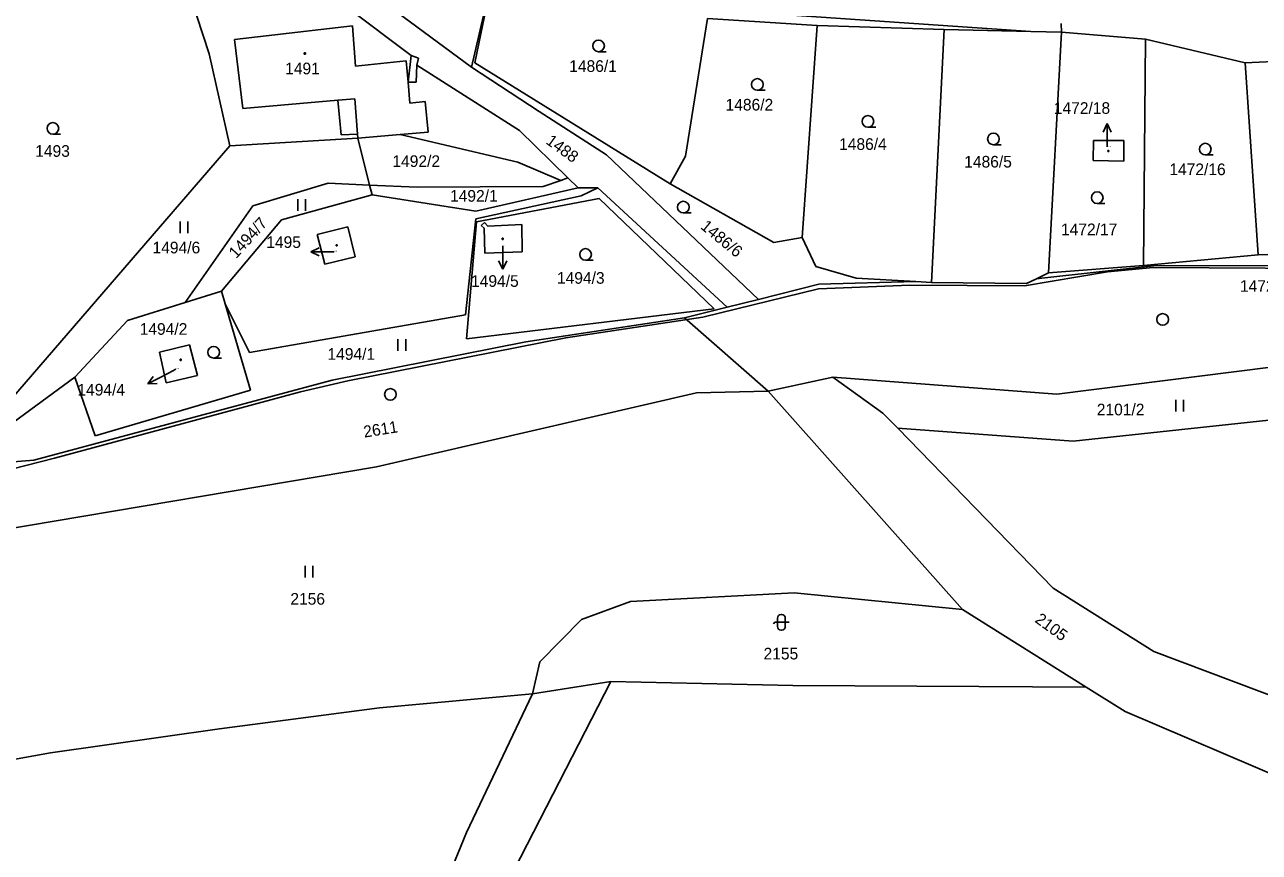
# Model space of a CAD drawing. Extents: x -805730 to -804640, y -1150889 to -1150366.
# Drawn here: x -805353.5 to -805194.5, y -1150727 to -1150620.5 of the extents above; entities that cross this region are included whole.
import ezdxf

# ---------------------------------------------------------------- set-up
doc = ezdxf.new("R2010")
doc.units = 0
for name, color, linetype in [('Default', 7, 'Continuous'), ('kilometráž - vrstava 7', 7, 'Continuous'), ('kn_celek - Cisla parcel pomocna', 7, 'Continuous'), ('kn_celek - Cisla pozemkovych parcel', 7, 'Continuous'), ('kn_celek - Cisla stavebnich parcel', 7, 'Continuous'), ('kn_celek - Hranice parcel', 7, 'Continuous'), ('kn_celek - Vnitrni kresby', 7, 'Continuous'), ('kn_celek - Znacky budov', 7, 'Continuous'), ('kn_celek - Znacky kultur', 7, 'Continuous'), ('plochy - SZDC', 7, 'Continuous'), ('PSR_C2_2_trasa_Vimperk - Kabelová trasa', 7, 'Continuous')]:
    doc.layers.add(name, color=color, linetype=linetype)

# ---------------------------------------------------------------- blocks, each defined once
blk = doc.blocks.new('304')
at = {"layer": 'Default'}
blk.add_line((-0.1, 0), (9.9, 0), dxfattribs=at)
blk.add_circle((-0.1, 7.5), 7.5, dxfattribs=at)
blk = doc.blocks.new('306')
at = {"layer": 'Default'}
for p, q in [((-5.2, 0), (-5.2, 15)), ((4.8, 0), (4.8, 15))]:
    blk.add_line(p, q, dxfattribs=at)
blk = doc.blocks.new('316')
at = {"layer": 'Default'}
for p, q in [((0.5, 20), (-0.5, 20)), ((-8.3, 10), (-10, 8.1)), ((-5, 10), (-8.3, 10)), ((-5, 15.5), (-5, 4.5)), ((-5, 10), (5, 10)), ((-0.5, 0), (0.5, 0)), ((5, 4.5), (5, 15.5)), ((10, 10), (5, 10))]:
    blk.add_line(p, q, dxfattribs=at)
for centre, start, end in [((-0.5, 15.5), 90, 180), ((0.5, 15.5), 0, 90), ((-0.5, 4.5), 180, 270), ((0.5, 4.5), 270, 0)]:
    blk.add_arc(centre, 4.5, start, end, dxfattribs=at)
blk = doc.blocks.new('402')
at = {"layer": 'Default'}
for p, q in [((-0.8, 0.8), (0.7, 0.8)), ((-0.8, 0.8), (-0.8, -0.7)), ((0.7, 0.8), (0.7, -0.7)), ((0.7, -0.7), (-0.8, -0.7))]:
    blk.add_line(p, q, dxfattribs=at)
blk = doc.blocks.new('Z61')
at = {"layer": 'Default'}
for p, q in [((0, 0), (30, 0)), ((30, 0), (19.2, 5.3)), ((30, 0), (19.2, -5.3))]:
    blk.add_line(p, q, dxfattribs=at)

msp = doc.modelspace()

# ---------------------------------------------------------------- linework, layer by layer
at = {"layer": 'kilometráž - vrstava 7'}
for centre in [(-805206.98, -1150658.41), (-805306.42, -1150668.06)]:
    msp.add_circle(centre, 0.75, dxfattribs=at)
at = {"layer": 'kn_celek - Cisla parcel pomocna'}
msp.add_line((-805334.06, -1150664.81), (-805335, -1150665.31), dxfattribs=at)
at = {"layer": 'kn_celek - Hranice parcel'}
for p, q in [((-805329.77, -1150624.22), (-805333.04, -1150614.16)), ((-805310.84, -1150614.97), (-805295.98, -1150625.93)), ((-805295.98, -1150625.93), (-805293.82, -1150616.59)), ((-805293.75, -1150616.59), (-805295.53, -1150625.4)), ((-805303.74, -1150624.45), (-805312.03, -1150618.23)), ((-805272.94, -1150618.01), (-805223.94, -1150621.35)), ((-805265.57, -1150619.68), (-805268.41, -1150637.4)), ((-805265.57, -1150619.68), (-805251.46, -1150620.59)), ((-805253.39, -1150647.87), (-805251.46, -1150620.59)), ((-805251.46, -1150620.59), (-805235.12, -1150621.11)), ((-805235.12, -1150621.11), (-805236.73, -1150653.66)), ((-805235.12, -1150621.11), (-805223.94, -1150621.35)), ((-805220.01, -1150621.44), (-805223.94, -1150621.35)), ((-805220.01, -1150621.44), (-805221.67, -1150652.43)), ((-805220.01, -1150621.44), (-805220.03, -1150620.31)), ((-805220.01, -1150621.44), (-805209.21, -1150622.35)), ((-805209.21, -1150622.35), (-805209.44, -1150651.45)), ((-805209.21, -1150622.35), (-805196.37, -1150625.39)), ((-805329.77, -1150624.22), (-805327.08, -1150636.08)), ((-805303.74, -1150624.45), (-805302.8, -1150624.78)), ((-805302.8, -1150624.78), (-805303.02, -1150625.67)), ((-805196.37, -1150625.39), (-805183.26, -1150624.76)), ((-805289.81, -1150634.11), (-805303.02, -1150625.67)), ((-805295.98, -1150625.93), (-805287.25, -1150631.65)), ((-805270.38, -1150640.96), (-805295.53, -1150625.4)), ((-805196.37, -1150625.39), (-805194.7, -1150650.11)), ((-805287.25, -1150631.65), (-805278.6, -1150637.23)), ((-805283.55, -1150640.18), (-805289.81, -1150634.11)), ((-805310.6, -1150635.06), (-805327.08, -1150636.08)), ((-805310.6, -1150635.06), (-805305.16, -1150634.61)), ((-805309.1, -1150641.11), (-805310.6, -1150635.06)), ((-805305.16, -1150634.61), (-805290, -1150638.16)), ((-805215.94, -1150637.96), (-805215.89, -1150635.38)), ((-805215.89, -1150635.38), (-805212, -1150635.4)), ((-805212, -1150635.4), (-805212, -1150638.05)), ((-805362.8, -1150677.38), (-805327.08, -1150636.08)), ((-805278.6, -1150637.23), (-805259.03, -1150655.84)), ((-805268.41, -1150637.4), (-805270.38, -1150640.96)), ((-805284.49, -1150640.51), (-805290, -1150638.16)), ((-805212, -1150638.05), (-805215.94, -1150637.96)), ((-805286.74, -1150641.29), (-805284.49, -1150640.51)), ((-805284.49, -1150640.51), (-805283.55, -1150640.18)), ((-805282.22, -1150641.47), (-805283.55, -1150640.18)), ((-805314.43, -1150640.89), (-805324.14, -1150643.77)), ((-805320.46, -1150645.58), (-805308.78, -1150642.39)), ((-805309.1, -1150641.11), (-805314.43, -1150640.89)), ((-805308.78, -1150642.39), (-805309.1, -1150641.11)), ((-805302.95, -1150641.37), (-805309.1, -1150641.11)), ((-805308.78, -1150642.39), (-805295.4, -1150644.46)), ((-805286.74, -1150641.29), (-805302.95, -1150641.37)), ((-805295.4, -1150644.46), (-805282.22, -1150641.47)), ((-805282.22, -1150641.47), (-805279.69, -1150641.49)), ((-805279.69, -1150641.49), (-805281.84, -1150642.49)), ((-805279.69, -1150641.49), (-805263.04, -1150656.84)), ((-805270.38, -1150640.96), (-805257.03, -1150648.53)), ((-805324.14, -1150643.77), (-805332.84, -1150656.24)), ((-805295.42, -1150645.46), (-805281.84, -1150642.49)), ((-805279.55, -1150642.84), (-805295.32, -1150645.83)), ((-805279.55, -1150642.84), (-805264.71, -1150657.04)), ((-805328.16, -1150654.79), (-805320.46, -1150645.58)), ((-805295.42, -1150645.46), (-805296.73, -1150657.84)), ((-805295.32, -1150645.83), (-805296.63, -1150660.91)), ((-805294.74, -1150646.34), (-805294.28, -1150645.95)), ((-805294.35, -1150646.65), (-805294.74, -1150646.34)), ((-805294.25, -1150649.87), (-805294.35, -1150646.65)), ((-805294.28, -1150645.95), (-805293.87, -1150646.39)), ((-805293.87, -1150646.39), (-805289.51, -1150646.21)), ((-805289.51, -1150646.21), (-805289.44, -1150649.72)), ((-805257.03, -1150648.53), (-805253.39, -1150647.87)), ((-805251.65, -1150651.59), (-805253.39, -1150647.87)), ((-805289.44, -1150649.72), (-805294.25, -1150649.87)), ((-805209.44, -1150651.45), (-805194.7, -1150650.11)), ((-805194.7, -1150650.11), (-805180.04, -1150649.49)), ((-805246.46, -1150653.1), (-805251.65, -1150651.59)), ((-805222.55, -1150653.1), (-805208.17, -1150651.53)), ((-805221.67, -1150652.43), (-805209.44, -1150651.45)), ((-805178.93, -1150651.45), (-805208.17, -1150651.53)), ((-805238.75, -1150653.54), (-805246.46, -1150653.1)), ((-805223.22, -1150653.17), (-805224.51, -1150653.79)), ((-805221.67, -1150652.43), (-805223.22, -1150653.17)), ((-805223.22, -1150653.17), (-805222.55, -1150653.1)), ((-805332.84, -1150656.24), (-805328.16, -1150654.79)), ((-805328.16, -1150654.79), (-805327.68, -1150656.42)), ((-805259.03, -1150655.84), (-805251.25, -1150653.89)), ((-805251.25, -1150653.89), (-805238.75, -1150653.54)), ((-805236.73, -1150653.66), (-805238.75, -1150653.54)), ((-805224.51, -1150653.79), (-805236.73, -1150653.66)), ((-805340.26, -1150658.54), (-805332.84, -1150656.24)), ((-805327.68, -1150656.42), (-805324.43, -1150667.5)), ((-805327.68, -1150656.42), (-805324.56, -1150662.66)), ((-805263.04, -1150656.84), (-805259.03, -1150655.84)), ((-805296.73, -1150657.84), (-805324.56, -1150662.66)), ((-805296.63, -1150660.91), (-805264.71, -1150657.04)), ((-805288.99, -1150661.29), (-805268.53, -1150658.22)), ((-805268.53, -1150658.22), (-805263.04, -1150656.84)), ((-805268.53, -1150658.22), (-805257.77, -1150667.64)), ((-805347.06, -1150665.86), (-805340.26, -1150658.54)), ((-805313.93, -1150666.21), (-805288.99, -1150661.29)), ((-805336.17, -1150662.61), (-805332.28, -1150661.68)), ((-805335.28, -1150666.58), (-805336.17, -1150662.61)), ((-805332.28, -1150661.68), (-805331.27, -1150665.63)), ((-805220.59, -1150668.04), (-805193.03, -1150664.54)), ((-805362.8, -1150677.38), (-805347.06, -1150665.86)), ((-805313.93, -1150666.21), (-805352.32, -1150676.52)), ((-805344.42, -1150673.39), (-805347.06, -1150665.86)), ((-805331.27, -1150665.63), (-805335.28, -1150666.58)), ((-805257.77, -1150667.64), (-805249.45, -1150665.86)), ((-805249.45, -1150665.86), (-805220.59, -1150668.04)), ((-805249.45, -1150665.86), (-805243, -1150670.46)), ((-805344.42, -1150673.39), (-805324.43, -1150667.5)), ((-805267.02, -1150667.87), (-805257.77, -1150667.64)), ((-805257.77, -1150667.64), (-805232.77, -1150695.74)), ((-805308.19, -1150677.39), (-805267.02, -1150667.87)), ((-805243, -1150670.46), (-805241.07, -1150672.41)), ((-805218.5, -1150674.08), (-805189.9, -1150671)), ((-805241.07, -1150672.41), (-805218.5, -1150674.08)), ((-805241.07, -1150672.41), (-805221.06, -1150693)), ((-805362.8, -1150677.38), (-805352.32, -1150676.52)), ((-805358.57, -1150685.85), (-805308.19, -1150677.39)), ((-805221.06, -1150693), (-805208.12, -1150701.15)), ((-805281.82, -1150697.05), (-805275.5, -1150694.72)), ((-805275.5, -1150694.72), (-805254.41, -1150693.59)), ((-805232.77, -1150695.74), (-805254.41, -1150693.59)), ((-805232.77, -1150695.74), (-805216.83, -1150705.76)), ((-805287.18, -1150702.5), (-805281.82, -1150697.05)), ((-805208.12, -1150701.15), (-805186.47, -1150709.31)), ((-805288.11, -1150706.61), (-805287.18, -1150702.5)), ((-805278.05, -1150705.01), (-805290.48, -1150729.27)), ((-805278.05, -1150705.01), (-805288.11, -1150706.61)), ((-805254.58, -1150705.52), (-805278.05, -1150705.01)), ((-805230.66, -1150705.67), (-805254.58, -1150705.52)), ((-805216.83, -1150705.76), (-805230.66, -1150705.67)), ((-805211.82, -1150708.9), (-805216.83, -1150705.76)), ((-805307.83, -1150708.43), (-805288.11, -1150706.61)), ((-805296.6, -1150724.44), (-805288.11, -1150706.61)), ((-805328.43, -1150711.11), (-805307.83, -1150708.43)), ((-805185.27, -1150720.22), (-805211.82, -1150708.9)), ((-805350.19, -1150714.2), (-805328.43, -1150711.11)), ((-805369.54, -1150717.67), (-805350.19, -1150714.2)), ((-805305.52, -1150746.02), (-805296.6, -1150724.44))]:
    msp.add_line(p, q, dxfattribs=at)
at = {"layer": 'kn_celek - Vnitrni kresby'}
for p, q in [((-805326.49, -1150622.4), (-805311.29, -1150620.64)), ((-805311.29, -1150620.64), (-805310.93, -1150625.8)), ((-805325.44, -1150631.26), (-805326.49, -1150622.4)), ((-805303.74, -1150624.45), (-805304.15, -1150627.87)), ((-805310.93, -1150625.8), (-805304.38, -1150625.11)), ((-805304.38, -1150625.11), (-805304.15, -1150627.87)), ((-805303.02, -1150625.67), (-805303.1, -1150627.89)), ((-805303.1, -1150627.89), (-805304.15, -1150627.87)), ((-805304.15, -1150627.87), (-805303.92, -1150630.59)), ((-805325.44, -1150631.26), (-805313.18, -1150630.2)), ((-805313.18, -1150630.2), (-805311.01, -1150630.01)), ((-805312.75, -1150634.63), (-805313.18, -1150630.2)), ((-805310.64, -1150634.56), (-805311.01, -1150630.01)), ((-805303.92, -1150630.59), (-805301.96, -1150630.37)), ((-805301.96, -1150630.37), (-805301.56, -1150634.32)), ((-805301.56, -1150634.32), (-805305.16, -1150634.61)), ((-805310.64, -1150634.56), (-805312.75, -1150634.63)), ((-805310.6, -1150635.06), (-805310.64, -1150634.56)), ((-805315.86, -1150647.46), (-805311.91, -1150646.48)), ((-805311.91, -1150646.48), (-805310.94, -1150650.34)), ((-805314.84, -1150651.32), (-805315.86, -1150647.46)), ((-805310.94, -1150650.34), (-805314.84, -1150651.32))]:
    msp.add_line(p, q, dxfattribs=at)
at = {"layer": 'plochy - SZDC'}
for p, q in [((-805208.17, -1150651.53), (-805222.55, -1150653.1)), ((-805178.93, -1150651.45), (-805208.17, -1150651.53)), ((-805223.22, -1150653.17), (-805224.51, -1150653.79)), ((-805222.55, -1150653.1), (-805223.22, -1150653.17)), ((-805251.25, -1150653.89), (-805259.03, -1150655.84)), ((-805238.75, -1150653.54), (-805251.25, -1150653.89)), ((-805236.73, -1150653.66), (-805238.75, -1150653.54)), ((-805224.51, -1150653.79), (-805236.73, -1150653.66)), ((-805259.03, -1150655.84), (-805263.04, -1150656.84)), ((-805268.53, -1150658.22), (-805288.99, -1150661.29)), ((-805263.04, -1150656.84), (-805268.53, -1150658.22)), ((-805257.77, -1150667.64), (-805268.53, -1150658.22)), ((-805268.53, -1150658.22), (-805257.77, -1150667.64)), ((-805288.99, -1150661.29), (-805313.93, -1150666.21)), ((-805220.59, -1150668.04), (-805193.03, -1150664.54)), ((-805313.93, -1150666.21), (-805352.32, -1150676.52)), ((-805257.77, -1150667.64), (-805249.45, -1150665.86)), ((-805249.45, -1150665.86), (-805220.59, -1150668.04)), ((-805267.02, -1150667.87), (-805257.77, -1150667.64)), ((-805308.19, -1150677.39), (-805267.02, -1150667.87)), ((-805352.32, -1150676.52), (-805362.8, -1150677.38)), ((-805358.57, -1150685.85), (-805308.19, -1150677.39))]:
    msp.add_line(p, q, dxfattribs=at)
at = {"layer": 'PSR_C2_2_trasa_Vimperk - Kabelová trasa'}
for points in [[(-805214.1, -1150652.28), (-805208.19, -1150651.74), (-805179.31, -1150651.91), (-805164.88, -1150649.95), (-805150.36, -1150646.9), (-805138.79, -1150644.66), (-805134.9, -1150644.97), (-805132.95, -1150644.53), (-805122.45, -1150641.59)], [(-805239.52, -1150653.99), (-805224.76, -1150654.07), (-805214.1, -1150652.28)], [(-805372.22, -1150682.03), (-805349.68, -1150676.27), (-805317.98, -1150667.75), (-805311.89, -1150666.33), (-805283.81, -1150660.76), (-805266.17, -1150658.11), (-805251.29, -1150654.49), (-805239.52, -1150653.99)]]:
    msp.add_lwpolyline(points, dxfattribs=at)

# ---------------------------------------------------------------- block references
at = {"layer": 'kn_celek - Cisla parcel pomocna', "xscale": 0.1}
for p, yscale, rotation in [((-805214.13, -1150636.21), 0.10000000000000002, 90.00000000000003), ((-805313.65, -1150649.71), 0.10000000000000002, -179.99999999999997), ((-805291.95, -1150648.96), 0.10000000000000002, -90.00000000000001), ((-805335, -1150665.31), 0.09999999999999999, -152.11008000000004)]:
    msp.add_blockref('Z61', p, dxfattribs=dict(at, yscale=yscale, rotation=rotation))
at = {"layer": 'kn_celek - Znacky budov', "xscale": 0.1, "yscale": 0.10000000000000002}
for p in [(-805317.43, -1150624.19), (-805213.96, -1150636.74), (-805291.95, -1150648.04), (-805313.33, -1150648.89), (-805333.42, -1150663.62)]:
    msp.add_blockref('402', p, dxfattribs=at)
at = {"layer": 'kn_celek - Znacky kultur', "xscale": 0.1, "yscale": 0.10000000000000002}
for name, p in [('304', (-805279.61, -1150623.95)), ('304', (-805259.16, -1150628.92)), ('304', (-805244.92, -1150633.67)), ('304', (-805349.87, -1150634.57)), ('304', (-805228.76, -1150635.93)), ('304', (-805201.48, -1150637.24)), ('304', (-805215.4, -1150643.49)), ('306', (-805317.83, -1150644.42)), ('304', (-805268.69, -1150644.71)), ('306', (-805332.98, -1150647.31)), ('304', (-805281.28, -1150650.8)), ('306', (-805304.93, -1150662.45)), ('304', (-805329.16, -1150663.39)), ('306', (-805204.77, -1150670.27)), ('306', (-805316.89, -1150691.64)), ('316', (-805256.07, -1150698.4))]:
    msp.add_blockref(name, p, dxfattribs=at)

# ---------------------------------------------------------------- texts
at = {"layer": 'kn_celek - Cisla parcel pomocna'}
for s, p in [('1472/18', (-805220.99, -1150631.95)), ('1495', (-805322.4, -1150649.21)), ('1494/5', (-805296.03, -1150654.22)), ('1472/21', (-805197.03, -1150654.86)), ('1494/4', (-805346.72, -1150668.21))]:
    msp.add_text(s, height=1.5, dxfattribs=at).set_placement(p)
at = {"layer": 'kn_celek - Cisla pozemkovych parcel'}
for s, p in [('1486/1', (-805283.39, -1150626.55)), ('1486/2', (-805263.26, -1150631.52)), ('1493', (-805352.15, -1150637.48)), ('1486/4', (-805248.64, -1150636.59)), ('1492/2', (-805306.16, -1150638.79)), ('1486/5', (-805232.53, -1150638.86)), ('1472/16', (-805206.12, -1150639.84)), ('1492/1', (-805298.74, -1150643.26)), ('1472/17', (-805220.07, -1150647.57)), ('1494/6', (-805337.04, -1150649.91)), ('1494/3', (-805284.97, -1150653.82)), ('1494/2', (-805338.7, -1150660.39)), ('1494/1', (-805314.52, -1150663.61)), ('2101/2', (-805215.46, -1150670.76)), ('2156', (-805319.3, -1150695.13)), ('2155', (-805258.37, -1150702.18))]:
    msp.add_text(s, height=1.5, dxfattribs=at).set_placement(p)
for s, rotation, p in [('1488', 324, (-805286.51, -1150635.7)), ('1494/7', 47.6209, (-805326.28, -1150650.66)), ('1486/6', 320.5756, (-805266.59, -1150646.63)), ('2611', 9, (-805309.77, -1150673.63)), ('2105', 324, (-805223.54, -1150697.29))]:
    msp.add_text(s, height=1.5, rotation=rotation, dxfattribs=at).set_placement(p)
at = {"layer": 'kn_celek - Cisla stavebnich parcel'}
for s, height, p in [('1491', 1.5, (-805319.97, -1150626.86)), ('1472/18', 0.1, (-805214.13, -1150636.18)), ('1495', 0.1, (-805313.65, -1150649.68)), ('1494/5', 0.1, (-805291.95, -1150648.93)), ('1494/4', 0.1, (-805334.06, -1150664.78))]:
    msp.add_text(s, height=height, dxfattribs=at).set_placement(p)

doc.saveas('drawing.dxf')
